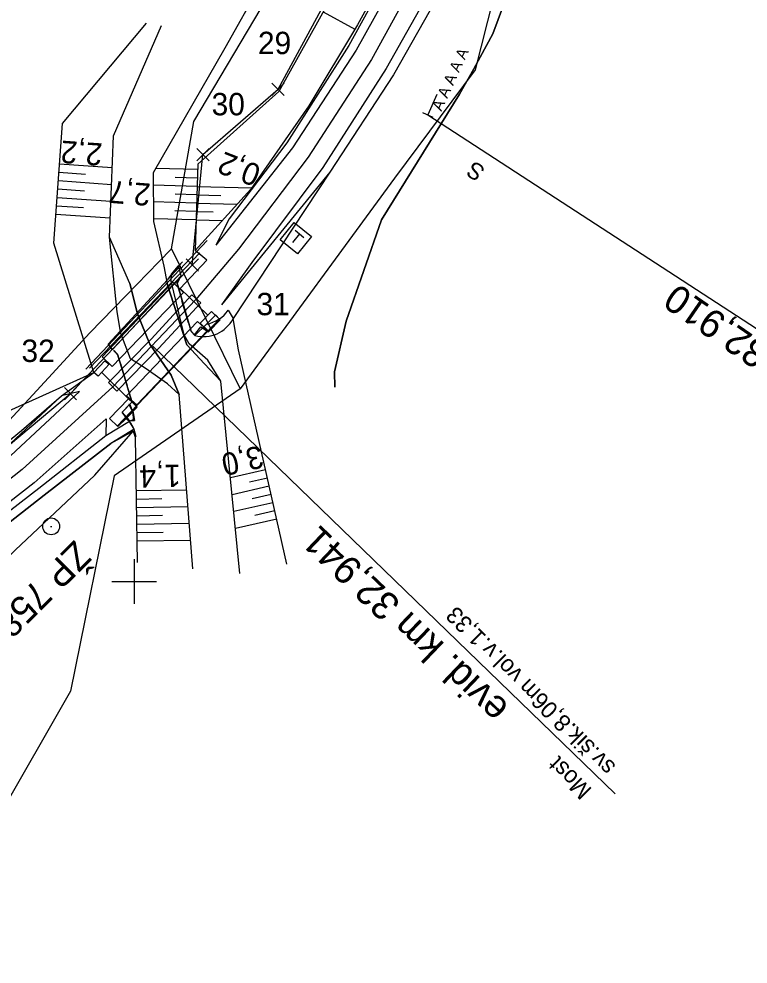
# Model space of a CAD drawing. Extents: x -804166 to -803706, y -1151030 to -1150147.
# Drawn here: x -803910.3 to -803845.1, y -1150734.2 to -1150649.7 of the extents above; entities that cross this region are included whole.
import ezdxf

# ---------------------------------------------------------------- set-up
doc = ezdxf.new("R2010")
doc.units = 0
for name, color, linetype in [('0381KM032-037P - Vrstva 1', 7, 'Continuous'), ('0381KM032-037P - Vrstva 13', 7, 'Continuous'), ('0381KM032-037P - Vrstva 17', 7, 'Continuous'), ('0381KM032-037P - Vrstva 18', 7, 'Continuous'), ('0381KM032-037P - Vrstva 33', 7, 'Continuous'), ('0381KM032-037P - Vrstva 35', 7, 'Continuous'), ('0381KM032-037P - Vrstva 4', 7, 'Continuous'), ('0381KM032-037P - Vrstva 48', 7, 'Continuous'), ('0381KM032-037P - Vrstva 49', 7, 'Continuous'), ('0381KM032-037P - Vrstva 50', 7, 'Continuous'), ('0381KM032-037P - Vrstva 55', 7, 'Continuous'), ('0381KM032-037P - Vrstva 6', 7, 'Continuous'), ('Default', 7, 'Continuous'), ('hran DP - hran DP', 7, 'Continuous'), ('krizky_1000 - Vrstva 1', 7, 'Continuous'), ('PSR_C2_2_Lomove_body_Vimperk - Vrstva 60', 7, 'Continuous'), ('PSR_C2_2_trasa_Vimperk - Kabelová trasa', 7, 'Continuous'), ('vyt_sit - stávající', 7, 'Continuous')]:
    doc.layers.add(name, color=color, linetype=linetype)

msp = doc.modelspace()

# ---------------------------------------------------------------- linework, layer by layer
at = {"layer": '0381KM032-037P - Vrstva 1'}
msp.add_line((-803894.474, -1150674.768), (-803901.906, -1150682.605), dxfattribs=at)
for points in [[(-803862.645, -1150536.71), (-803860.057, -1150547.81), (-803858.364, -1150558.718), (-803857.51, -1150569.546), (-803857.425, -1150579.975), (-803858.096, -1150590.725), (-803859.58, -1150601.687), (-803861.73, -1150611.946), (-803864.691, -1150622.329), (-803868.306, -1150632.261), (-803873.118, -1150643.006), (-803878.784, -1150653.323), (-803884.455, -1150662.043), (-803890.68, -1150670.289), (-803894.474, -1150674.768)], [(-803901.906, -1150682.605), (-803910.014, -1150690), (-803918.643, -1150696.775), (-803928.041, -1150703.062), (-803937.946, -1150708.688), (-803946.795, -1150712.932), (-803956.655, -1150716.869), (-803966.853, -1150720.098), (-803973.694, -1150721.813), (-803983.505, -1150723.682), (-803993.918, -1150724.91), (-804004.459, -1150725.421), (-804014.948, -1150725.206), (-804025.475, -1150724.252), (-804035.41, -1150722.673), (-804044.081, -1150720.735), (-804054.774, -1150717.615), (-804061.472, -1150715.138)]]:
    msp.add_lwpolyline(points, dxfattribs=at)
at = {"layer": '0381KM032-037P - Vrstva 13'}
for p, q in [((-803900.427, -1150685.689), (-803900.743, -1150685.422)), ((-803900.427, -1150685.69), (-803902.54, -1150686.99)), ((-803900.02, -1150686.371), (-803900.089, -1150686.205)), ((-803900.019, -1150686.37), (-803902.092, -1150687.65))]:
    msp.add_line(p, q, dxfattribs=at)
for points in [[(-803900.743, -1150685.422), (-803900.692, -1150685.394), (-803900.742, -1150685.419)], [(-803900.02, -1150686.371), (-803899.851, -1150687.044), (-803899.848, -1150687.042), (-803900.019, -1150686.37), (-803900.427, -1150685.69), (-803900.742, -1150685.419)], [(-803900.089, -1150686.205), (-803900.081, -1150686.195), (-803900.317, -1150685.837), (-803900.317, -1150685.836), (-803900.427, -1150685.689)], [(-803902.54, -1150686.99), (-803908.533, -1150691.682), (-803917.537, -1150698.646), (-803926.885, -1150705.063), (-803937.003, -1150710.487), (-803946.017, -1150714.661), (-803956.263, -1150718.85), (-803966.288, -1150722.189), (-803972.538, -1150724.259)], [(-803972.286, -1150725.012), (-803966.125, -1150722.974), (-803955.955, -1150719.581), (-803945.709, -1150715.376), (-803936.565, -1150711.19), (-803926.506, -1150705.78), (-803917.073, -1150699.315), (-803908.044, -1150692.29), (-803902.092, -1150687.65)]]:
    msp.add_lwpolyline(points, dxfattribs=at)
at = {"layer": '0381KM032-037P - Vrstva 17'}
for p, q in [((-803903.995, -1150680.91), (-803894.145, -1150670.618)), ((-803892.37, -1150676.505), (-803901.521, -1150686.105))]:
    msp.add_line(p, q, dxfattribs=at)
for points in [[(-803867.911, -1150651.01), (-803864.194, -1150640.965), (-803863.34, -1150639.848), (-803860.107, -1150635.351), (-803857.384, -1150629.008), (-803845.634, -1150598.77), (-803839.769, -1150573.178), (-803837.289, -1150572.72)], [(-803882.068, -1150682.623), (-803882.094, -1150681.238), (-803881.038, -1150676.732), (-803877.877, -1150667.643), (-803870.889, -1150656.426), (-803869.632, -1150654.159), (-803867.911, -1150651.01)]]:
    msp.add_lwpolyline(points, dxfattribs=at)
at = {"layer": '0381KM032-037P - Vrstva 18'}
for p, q in [((-803902.321, -1150678.769), (-803895.977, -1150671.88)), ((-803895.96, -1150671.875), (-803897.006, -1150672.976)), ((-803895.972, -1150671.746), (-803896.032, -1150671.776)), ((-803895.788, -1150672.67), (-803901.935, -1150679.269)), ((-803896.656, -1150672.511), (-803897.006, -1150672.976)), ((-803895.788, -1150672.67), (-803895.788, -1150672.67)), ((-803895.902, -1150673.797), (-803893.451, -1150676.167)), ((-803895.155, -1150676.86), (-803895.737, -1150674.89)), ((-803892.742, -1150676.15), (-803892.333, -1150676.585)), ((-803891.585, -1150675.741), (-803891.14, -1150676.484)), ((-803893.531, -1150676.988), (-803894.581, -1150678.003)), ((-803892.333, -1150676.585), (-803893.36, -1150677.66)), ((-803892.31, -1150676.591), (-803892.333, -1150676.585)), ((-803893.36, -1150677.66), (-803893.335, -1150677.645)), ((-803901.935, -1150679.269), (-803902.321, -1150678.769)), ((-803856.973, -1150719.009), (-803898.348, -1150678.956)), ((-803900.514, -1150683.661), (-803902.936, -1150681.284)), ((-803900.594, -1150682.547), (-803901.206, -1150680.55)), ((-803900.177, -1150683.94), (-803901.093, -1150684.85)), ((-803900.181, -1150683.948), (-803900.177, -1150683.94)), ((-803899.733, -1150684.407), (-803899.765, -1150684.362)), ((-803900.692, -1150685.394), (-803901.461, -1150686.142)), ((-803900.692, -1150685.394), (-803901.093, -1150684.85)), ((-803900.087, -1150684.927), (-803900.086, -1150684.886)), ((-803900.387, -1150685.649), (-803899.968, -1150685.591))]:
    msp.add_line(p, q, dxfattribs=at)
for points in [[(-803895.902, -1150673.797), (-803893.509, -1150671.262), (-803894.538, -1150670.386)], [(-803892.244, -1150682.081), (-803893.405, -1150680.212), (-803895.1, -1150678.76), (-803895.543, -1150677.939), (-803896.702, -1150673.136), (-803896.656, -1150672.511), (-803896.032, -1150671.776)], [(-803894.595, -1150677.949), (-803894.892, -1150677.628), (-803896.154, -1150673.353), (-803896.156, -1150673.313), (-803895.788, -1150672.67), (-803896.032, -1150671.776), (-803895.682, -1150671.402), (-803895.972, -1150671.746), (-803895.977, -1150671.88)], [(-803896.154, -1150673.353), (-803895.788, -1150672.67), (-803895.977, -1150671.88)], [(-803895.96, -1150671.875), (-803896.006, -1150671.732), (-803896.032, -1150671.776)], [(-803902.876, -1150679.904), (-803896.545, -1150673.237), (-803895.586, -1150674.167), (-803901.958, -1150680.766), (-803902.876, -1150679.904)], [(-803896.156, -1150673.313), (-803894.92, -1150677.658), (-803894.581, -1150678.003)], [(-803902.301, -1150682.211), (-803901.541, -1150682.984), (-803897.786, -1150679.126), (-803894.042, -1150675.093), (-803894.835, -1150674.357), (-803898.482, -1150678.342), (-803902.301, -1150682.211)], [(-803892.31, -1150676.591), (-803893.094, -1150675.842), (-803894.104, -1150676.91), (-803893.335, -1150677.645), (-803892.31, -1150676.591)], [(-803892.742, -1150676.15), (-803892.697, -1150676.16), (-803893.531, -1150676.988)], [(-803900.704, -1150683.386), (-803899.78, -1150684.198), (-803893.446, -1150677.55), (-803894.353, -1150676.739), (-803900.704, -1150683.386)], [(-803894.581, -1150678.003), (-803894.595, -1150677.949), (-803894.041, -1150677.229), (-803894.041, -1150677.229), (-803893.36, -1150677.66)], [(-803901.935, -1150679.269), (-803901.931, -1150679.271), (-803902.334, -1150678.769), (-803902.321, -1150678.769)], [(-803900.181, -1150683.948), (-803901.502, -1150679.684), (-803901.835, -1150679.365), (-803901.815, -1150679.357), (-803901.461, -1150679.762), (-803900.212, -1150683.983), (-803900.181, -1150683.948)], [(-803902.232, -1150680.579), (-803903.222, -1150681.645), (-803903.605, -1150681.318), (-803902.621, -1150680.279), (-803902.232, -1150680.579)], [(-803899.765, -1150684.362), (-803901.461, -1150686.142), (-803902.204, -1150685.415), (-803900.514, -1150683.661), (-803899.765, -1150684.362)], [(-803901.093, -1150684.85), (-803901.09, -1150684.852), (-803900.467, -1150684.209), (-803900.408, -1150684.126), (-803900.086, -1150684.886), (-803899.968, -1150685.591), (-803900.061, -1150685.507), (-803900.087, -1150684.927), (-803900.467, -1150684.209)], [(-803900.177, -1150683.94), (-803899.733, -1150684.407), (-803900.692, -1150685.394)], [(-803901.09, -1150684.852), (-803900.387, -1150685.649), (-803900.061, -1150685.507)]]:
    msp.add_lwpolyline(points, dxfattribs=at)
for centre, major_axis, ratio, start_param, end_param in [((-803893.838, -1150674.452), (2.475, 1.269), 0.908828, 4.38934, 5.247205), ((-803893.887, -1150674.932), (1.395, -2.862), 0.971802, 5.593201, 6.899505)]:
    msp.add_ellipse(centre, major_axis=major_axis, ratio=ratio, start_param=start_param, end_param=end_param, dxfattribs=at)
at = {"layer": '0381KM032-037P - Vrstva 33'}
for p, q in [((-803885.617, -1150668.595), (-803884.838, -1150669.222)), ((-803885.227, -1150668.909), (-803885.855, -1150669.687))]:
    msp.add_line(p, q, dxfattribs=at)
msp.add_lwpolyline([(-803885.693, -1150667.892), (-803884.135, -1150669.146), (-803885.389, -1150670.704), (-803886.947, -1150669.45), (-803885.693, -1150667.892)], dxfattribs=at)
at = {"layer": '0381KM032-037P - Vrstva 35'}
msp.add_line((-803904.333, -1150681.001), (-803893.471, -1150669.506), dxfattribs=at)
at = {"layer": '0381KM032-037P - Vrstva 4'}
for points in [[(-803862.041, -1150601.171), (-803863.934, -1150611.478), (-803866.955, -1150621.666), (-803870.636, -1150631.623), (-803875.322, -1150642.112), (-803880.813, -1150652.073), (-803886.36, -1150660.761), (-803891.5, -1150667.581), (-803892.695, -1150669.921)], [(-803861.107, -1150601.386), (-803863.249, -1150611.592), (-803866.278, -1150621.841), (-803869.683, -1150631.826), (-803874.548, -1150642.393), (-803880.159, -1150652.477), (-803885.847, -1150661.208), (-803892.695, -1150669.921)], [(-803858.016, -1150602.009), (-803860.157, -1150612.315), (-803863.229, -1150623.106), (-803866.722, -1150632.775), (-803871.621, -1150643.742), (-803877.472, -1150654.13), (-803883.137, -1150662.978), (-803889.477, -1150671.458), (-803892.178, -1150675.246)], [(-803857.109, -1150602.102), (-803859.611, -1150612.518), (-803862.49, -1150623.34), (-803866.1, -1150633.182), (-803870.873, -1150644.181), (-803876.806, -1150654.687), (-803882.51, -1150663.405), (-803892.178, -1150675.246)], [(-803904.886, -1150683.001), (-803906.516, -1150683.391), (-803911.518, -1150688.069), (-803920.109, -1150694.835), (-803929.412, -1150700.935), (-803939.155, -1150706.209), (-803947.889, -1150710.398), (-803957.601, -1150714.533), (-803967.413, -1150717.637)], [(-803904.886, -1150683.001), (-803911.05, -1150688.735), (-803919.705, -1150695.384), (-803929.087, -1150701.477), (-803938.787, -1150707.105), (-803947.481, -1150711.337), (-803957.418, -1150715.321), (-803967.176, -1150718.433)], [(-803902.503, -1150685.469), (-803908.943, -1150691.185), (-803917.694, -1150697.991), (-803927.241, -1150704.348), (-803937.195, -1150710.055), (-803946.246, -1150714.302), (-803956.405, -1150718.419), (-803966.448, -1150721.526)], [(-803902.503, -1150685.469), (-803902.54, -1150686.99), (-803908.533, -1150691.682), (-803917.537, -1150698.646), (-803926.885, -1150705.063), (-803937.003, -1150710.487), (-803946.017, -1150714.661), (-803956.263, -1150718.85), (-803966.288, -1150722.189)]]:
    msp.add_lwpolyline(points, dxfattribs=at)
at = {"layer": '0381KM032-037P - Vrstva 48'}
for p, q in [((-803883.093, -1150649.037), (-803880.278, -1150650.604)), ((-803906.68, -1150662.653), (-803901.962, -1150662.988)), ((-803906.733, -1150663.401), (-803904.362, -1150663.569)), ((-803894.338, -1150663.165), (-803898.097, -1150663.061)), ((-803906.786, -1150664.149), (-803902.02, -1150664.487)), ((-803894.358, -1150663.915), (-803896.337, -1150663.86)), ((-803906.84, -1150664.897), (-803904.445, -1150665.067)), ((-803894.379, -1150664.664), (-803898.309, -1150664.555)), ((-803894.379, -1150664.664), (-803889.482, -1150664.8)), ((-803906.893, -1150665.645), (-803902.079, -1150665.987)), ((-803894.421, -1150666.164), (-803898.295, -1150666.056)), ((-803894.4, -1150665.414), (-803896.351, -1150665.36)), ((-803894.4, -1150665.414), (-803892.261, -1150665.473)), ((-803906.946, -1150666.394), (-803904.527, -1150666.565)), ((-803894.442, -1150666.913), (-803896.365, -1150666.86)), ((-803894.442, -1150666.913), (-803892.948, -1150666.955)), ((-803894.421, -1150666.164), (-803890.788, -1150666.265)), ((-803906.999, -1150667.142), (-803902.138, -1150667.487)), ((-803894.462, -1150667.663), (-803898.28, -1150667.557)), ((-803894.462, -1150667.663), (-803892.12, -1150667.728)), ((-803888.25, -1150690.03), (-803891.388, -1150690.739)), ((-803888.085, -1150690.761), (-803889.7, -1150691.126)), ((-803899.836, -1150691.878), (-803895.322, -1150691.802)), ((-803887.92, -1150691.493), (-803891.24, -1150692.243)), ((-803887.754, -1150692.224), (-803889.46, -1150692.61)), ((-803899.823, -1150692.628), (-803897.543, -1150692.589)), ((-803887.589, -1150692.956), (-803891.092, -1150693.748)), ((-803899.81, -1150693.378), (-803895.204, -1150693.3)), ((-803887.424, -1150693.688), (-803889.221, -1150694.094)), ((-803899.798, -1150694.128), (-803897.472, -1150694.088)), ((-803899.785, -1150694.878), (-803895.086, -1150694.798)), ((-803887.258, -1150694.419), (-803890.945, -1150695.252)), ((-803899.772, -1150695.628), (-803897.4, -1150695.587)), ((-803899.76, -1150696.377), (-803894.968, -1150696.296))]:
    msp.add_line(p, q, dxfattribs=at)
at = {"layer": '0381KM032-037P - Vrstva 49'}
for p, q in [((-803882.51, -1150663.405), (-803891.14, -1150676.484)), ((-803900.099, -1150686.57), (-803902.092, -1150687.65))]:
    msp.add_line(p, q, dxfattribs=at)
for points in [[(-803855.009, -1150569.422), (-803855.013, -1150580.14), (-803855.681, -1150591.137), (-803857.109, -1150602.102), (-803859.611, -1150612.518), (-803862.49, -1150623.34), (-803866.1, -1150633.182), (-803870.873, -1150644.181), (-803876.806, -1150654.687), (-803882.51, -1150663.405)], [(-803867.826, -1150615.469), (-803873.958, -1150632.621), (-803887.064, -1150656.172), (-803894.324, -1150662.675), (-803894.538, -1150670.386)], [(-803865.684, -1150616.069), (-803868.473, -1150625.045), (-803871.506, -1150633.468), (-803875.458, -1150641.91), (-803880.036, -1150650.199), (-803884.384, -1150657.469), (-803889.567, -1150664.922), (-803894.538, -1150670.386)], [(-803879.144, -1150629.624), (-803891.889, -1150652.288), (-803898.32, -1150663.448), (-803898.278, -1150667.796), (-803897.353, -1150671.802), (-803897.063, -1150673.395), (-803895.285, -1150678.85), (-803893.718, -1150680.524), (-803892.244, -1150682.081)], [(-803857.384, -1150629.008), (-803860.107, -1150635.351), (-803863.34, -1150639.848), (-803864.194, -1150640.965), (-803867.911, -1150651.01), (-803869.632, -1150654.159), (-803870.889, -1150656.426), (-803877.877, -1150667.643), (-803881.038, -1150676.732), (-803882.094, -1150681.238), (-803882.068, -1150682.623)], [(-803903.605, -1150681.318), (-803904.65, -1150677.954), (-803907.183, -1150669.738), (-803906.423, -1150659.026), (-803898.899, -1150650.067)], [(-803902.205, -1150669.209), (-803901.85, -1150660.131), (-803897.556, -1150650.259)], [(-803882.094, -1150681.238), (-803881.038, -1150676.732), (-803877.877, -1150667.643), (-803870.889, -1150656.426), (-803869.632, -1150654.159), (-803867.911, -1150651.01)], [(-803895.993, -1150683.294), (-803896.707, -1150681.538), (-803898.609, -1150678.776), (-803899.692, -1150676.05), (-803900.386, -1150673.352), (-803902.205, -1150669.209)], [(-803895.993, -1150683.294), (-803897.012, -1150682.314), (-803899.014, -1150680.911), (-803900.346, -1150680.09), (-803901.19, -1150677.817), (-803901.54, -1150675.88), (-803902.205, -1150669.209)], [(-803886.343, -1150698.471), (-803890.675, -1150679.297), (-803891.14, -1150676.484)], [(-803984.817, -1150721.442), (-803974.636, -1150719.233), (-803973.09, -1150718.927), (-803972.805, -1150718.807), (-803972.246, -1150718.741), (-803965.21, -1150716.746), (-803957.601, -1150714.533), (-803947.889, -1150710.398), (-803939.155, -1150706.209), (-803931.831, -1150702.119), (-803924.086, -1150697.218), (-803916.608, -1150691.841), (-803910.081, -1150686.51), (-803906.516, -1150683.391), (-803903.605, -1150681.318)], [(-803972.246, -1150718.741), (-803965.841, -1150714.337), (-803956.596, -1150711.219), (-803948.841, -1150707.727), (-803941.393, -1150704.085), (-803932.776, -1150700.061), (-803925.787, -1150694.954), (-803918.146, -1150689.679), (-803911.549, -1150684.903), (-803903.605, -1150681.318)], [(-803890.546, -1150699.304), (-803892.24, -1150682.08)], [(-803894.766, -1150698.862), (-803895.993, -1150683.294)], [(-803973.24, -1150730.36), (-803966.718, -1150727.463), (-803955.163, -1150723.59), (-803942.536, -1150718.416), (-803927.909, -1150711.458), (-803917.773, -1150704.055), (-803910.649, -1150697.212), (-803903.52, -1150690.487), (-803900.099, -1150686.57)], [(-803900.099, -1150686.57), (-803899.917, -1150687.085), (-803899.727, -1150698.309)], [(-803902.092, -1150687.65), (-803908.044, -1150692.29), (-803917.073, -1150699.315), (-803926.506, -1150705.78), (-803936.565, -1150711.19), (-803945.709, -1150715.376), (-803955.955, -1150719.581), (-803966.125, -1150722.974), (-803972.286, -1150725.012), (-803974.7, -1150725.768), (-803983.368, -1150727.37), (-803993.836, -1150727.905), (-804004.989, -1150728.615), (-804004.868, -1150729.928), (-804012.985, -1150730.258), (-804018.762, -1150729.808), (-804029.792, -1150728.642), (-804054.152, -1150723.147), (-804060.274, -1150720.943)]]:
    msp.add_lwpolyline(points, dxfattribs=at)
at = {"layer": '0381KM032-037P - Vrstva 50'}
for points in [[(-803870.937, -1150611.902), (-803879.144, -1150629.624), (-803891.889, -1150652.288), (-803898.32, -1150663.448), (-803898.278, -1150667.796), (-803897.353, -1150671.802), (-803897.063, -1150673.395)], [(-803900.386, -1150673.352), (-803902.205, -1150669.209), (-803901.85, -1150660.131), (-803897.556, -1150650.259)], [(-803900.386, -1150673.352), (-803899.692, -1150676.05), (-803898.609, -1150678.776), (-803896.707, -1150681.538), (-803895.993, -1150683.294)], [(-803892.24, -1150682.08), (-803893.718, -1150680.524), (-803895.285, -1150678.85), (-803897.063, -1150673.395)], [(-803890.546, -1150699.304), (-803892.244, -1150682.081)], [(-803894.766, -1150698.862), (-803895.993, -1150683.294)]]:
    msp.add_lwpolyline(points, dxfattribs=at)
at = {"layer": '0381KM032-037P - Vrstva 55'}
msp.add_line((-803896.67, -1150670.26), (-803890.53, -1150682.77), dxfattribs=at)
at = {"layer": '0381KM032-037P - Vrstva 6'}
for p, q in [((-803872.924, -1150656.457), (-803873.746, -1150658.258)), ((-803874.201, -1150658.05), (-803873.291, -1150658.466)), ((-803873.746, -1150658.258), (-803837.626, -1150681.738))]:
    msp.add_line(p, q, dxfattribs=at)
at = {"layer": 'hran DP - hran DP'}
for p, q in [((-803894.67, -1150658.87), (-803877.2, -1150629.46)), ((-803866.11, -1150640.84), (-803869.51, -1150654.24)), ((-803869.51, -1150654.24), (-803876.72, -1150663.94)), ((-803896.67, -1150670.26), (-803894.67, -1150658.87)), ((-803876.72, -1150663.94), (-803890.53, -1150682.77)), ((-803897.8, -1150671.42), (-803896.67, -1150670.26)), ((-803900.74, -1150674.44), (-803897.8, -1150671.42)), ((-803903.98, -1150677.77), (-803900.74, -1150674.44)), ((-803907.67, -1150681.78), (-803903.98, -1150677.77)), ((-803914.58, -1150689.29), (-803907.67, -1150681.78)), ((-803890.53, -1150682.77), (-803901.78, -1150690.55)), ((-803901.78, -1150690.55), (-803905.7, -1150709.82)), ((-803905.7, -1150709.82), (-803919.68, -1150734.23))]:
    msp.add_line(p, q, dxfattribs=at)
at = {"layer": 'krizky_1000 - Vrstva 1'}
for points in [[(-803900, -1150698), (-803900, -1150702)], [(-803902, -1150700), (-803898, -1150700)]]:
    msp.add_lwpolyline(points, dxfattribs=at)
at = {"layer": 'PSR_C2_2_Lomove_body_Vimperk - Vrstva 60'}
for p, q in [((-803887.679, -1150656.531), (-803886.579, -1150655.431)), ((-803886.579, -1150656.531), (-803887.679, -1150655.431)), ((-803894.402, -1150662.367), (-803893.302, -1150661.267)), ((-803893.302, -1150662.367), (-803894.402, -1150661.267)), ((-803895.358, -1150672.25), (-803894.258, -1150671.15)), ((-803894.258, -1150672.25), (-803895.358, -1150671.15)), ((-803906.251, -1150683.746), (-803905.151, -1150682.646)), ((-803905.151, -1150683.746), (-803906.251, -1150682.646))]:
    msp.add_line(p, q, dxfattribs=at)
at = {"layer": 'PSR_C2_2_trasa_Vimperk - Kabelová trasa'}
for points in [[(-803893.852, -1150661.817), (-803887.129, -1150655.981), (-803874.412, -1150632.501), (-803867.826, -1150615.469)], [(-803940.055, -1150706.112), (-803933.551, -1150703.306), (-803923.822, -1150697.471), (-803916.468, -1150692.184), (-803905.701, -1150683.196), (-803894.808, -1150671.7), (-803893.852, -1150661.817)]]:
    msp.add_lwpolyline(points, dxfattribs=at)
at = {"layer": 'vyt_sit - stávající'}
msp.add_line((-803907.48, -1150695.075), (-803907.38, -1150695.075), dxfattribs=at)
msp.add_circle((-803907.43, -1150695.075), 0.756, dxfattribs=at)

# ---------------------------------------------------------------- texts
at = {"layer": '0381KM032-037P - Vrstva 18'}
for s, height, rotation, p in [('evid. km 32,941', 2.5, 136.38556, (-803866.362, -1150711.135)), ('sv.šik.8,06m vol.v.1,33', 1.5, 134.97726, (-803856.852, -1150716.475)), ('Most', 1.5, 134.97726, (-803858.974, -1150718.595))]:
    msp.add_text(s, height=height, rotation=rotation, dxfattribs=at).set_placement(p)
at = {"layer": '0381KM032-037P - Vrstva 48'}
for s, rotation, p in [('2,2', 175.94175, (-803902.788, -1150660.827)), ('0,2', 158.4103, (-803888.52, -1150662.876)), ('2,7', 175.55344, (-803898.475, -1150664.424)), ('3,0', 192.73114, (-803888.718, -1150687.818)), ('1,4', 180.96981, (-803895.839, -1150689.546))]:
    msp.add_text(s, height=2, rotation=rotation, dxfattribs=at).set_placement(p)
at = {"layer": '0381KM032-037P - Vrstva 6'}
for s, height, rotation, p in [('  A A A A A ', 1, 65.47944, (-803872.836, -1150658.673)), ('S', 1.5, 146.15257, (-803868.497, -1150663.067)), ('km 32,910', 2.5, 145.47944, (-803838.584, -1150682.1))]:
    msp.add_text(s, height=height, rotation=rotation, dxfattribs=at).set_placement(p)
at = {"layer": 'Default'}
for s, p in [('29', (-803888.933, -1150652.834)), ('30', (-803893.078, -1150658.308)), ('31', (-803889.06, -1150676.188)), ('32', (-803910.084, -1150680.37))]:
    msp.add_text(s, height=2, dxfattribs=at).set_placement(p)
at = {"layer": 'vyt_sit - stávající'}
msp.add_text('ŽP 758', height=2.4, rotation=225, dxfattribs=at).set_placement((-803905.333, -1150696.219))

doc.saveas('drawing.dxf')
